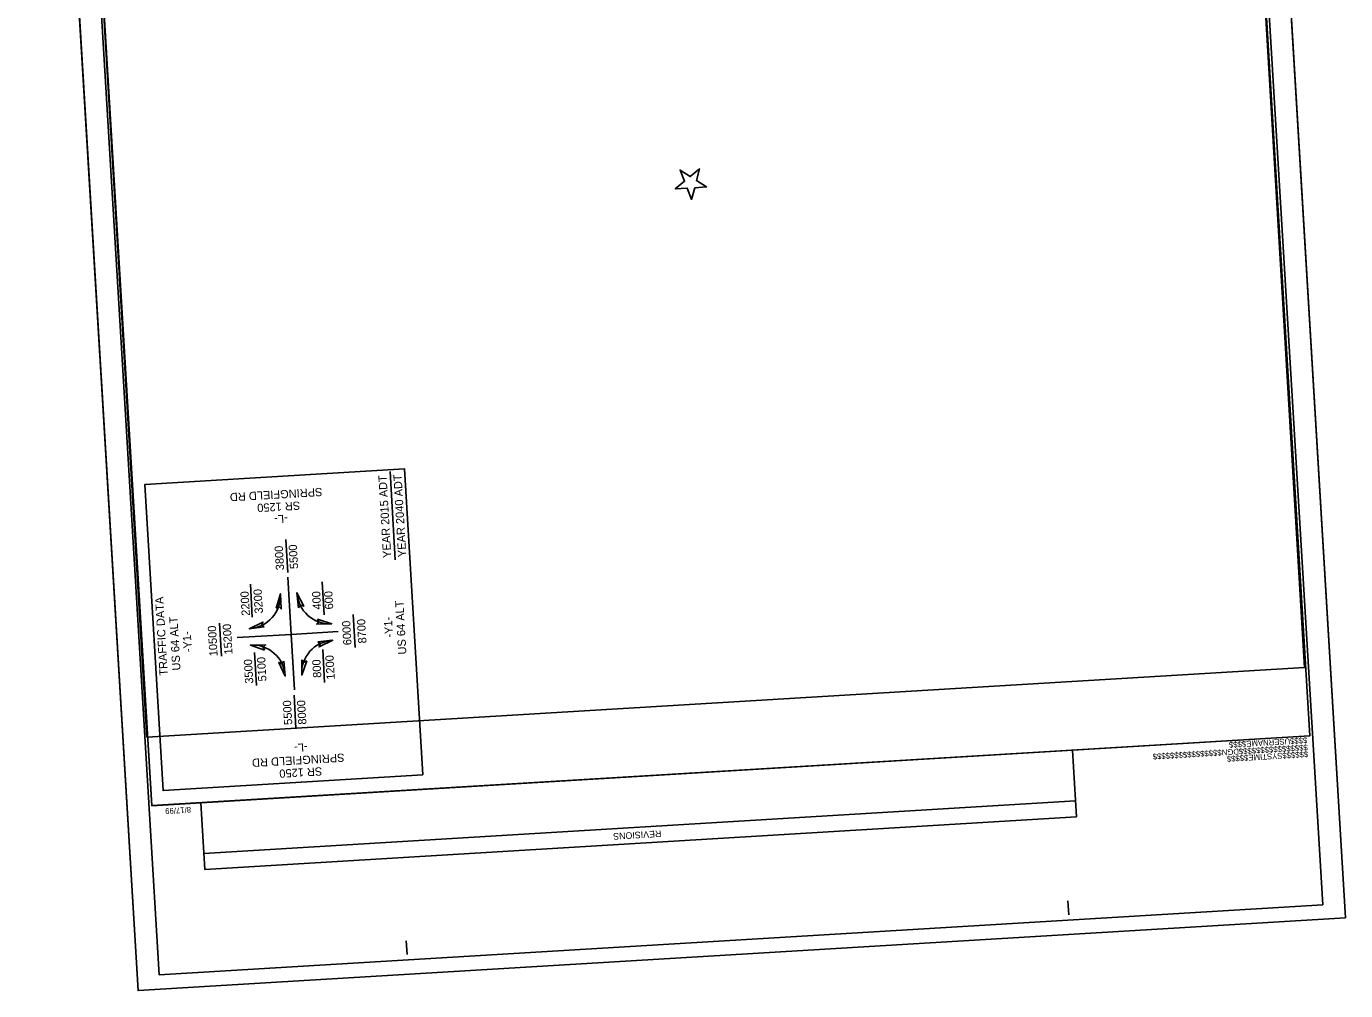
# Model space of a CAD drawing. Extents: x 2368361 to 2369555, y 800599 to 802345.
# Drawn here: x 2368361 to 2369555, y 800599 to 801472 of the extents above; entities that cross this region are included whole.
import ezdxf

# ---------------------------------------------------------------- set-up
doc = ezdxf.new("R2010")
doc.units = 0
for name, color, linetype in [('Old_Level_1', 7, 'Continuous'), ('Old_Level_10', 7, 'Continuous'), ('Old_Level_15', 7, 'Continuous'), ('Old_Level_2', 7, 'Continuous'), ('Old_Level_3', 7, 'Continuous'), ('Old_Level_4', 7, 'Continuous'), ('Old_Level_6', 7, 'Continuous'), ('Old_Level_7', 7, 'Continuous'), ('Plot Shape CELL', 7, 'Continuous'), ('User Information Notes CELL', 7, 'Continuous')]:
    doc.layers.add(name, color=color, linetype=linetype)

msp = doc.modelspace()

# ---------------------------------------------------------------- linework, layer by layer
at = {"layer": 'Old_Level_1'}
msp.add_lwpolyline([(2368966.2, 801326.1), (2368977, 801326.8), (2368967.9, 801332.6), (2368970.6, 801343.2), (2368962.2, 801336.3), (2368953, 801342.1), (2368957, 801332), (2368948.6, 801325.1), (2368959.4, 801325.7), (2368963.4, 801315.6), (2368966.2, 801326.1)], dxfattribs=at)
at = {"layer": 'Old_Level_10'}
msp.add_lwpolyline([(2368474.8, 800766.6), (2369522.9, 800829.7), (2369432.8, 802327), (2368595.8, 802276.7), (2368610.2, 802037.8), (2368399.1, 802025.1)], close=True, dxfattribs=at)
at = {"layer": 'Old_Level_15'}
for p, q in [((2369555.4, 800664.9), (2369454.3, 802345.4)), ((2368361.2, 802279.6), (2368462.3, 800599.1)), ((2368462.3, 800599.1), (2369555.4, 800664.9))]:
    msp.add_line(p, q, dxfattribs=at)
at = {"layer": 'Old_Level_2'}
msp.add_lwpolyline([(2368470.2, 800828.5), (2368399.1, 802025.1), (2368610.2, 802037.8), (2368599.6, 802213.8), (2369302.2, 802249.9), (2369298, 802318.9), (2369432.8, 802327), (2369518.3, 800891.6)], close=True, dxfattribs=at)
msp.add_lwpolyline([(2368470.2, 800828.5), (2368399.1, 802025.1), (2368610.2, 802037.8), (2368599.6, 802213.8), (2369302.2, 802249.9), (2369298, 802318.9), (2369432.8, 802327), (2369518.3, 800891.6)], close=True, dxfattribs=at)
at = {"layer": 'Old_Level_3'}
for points in [[(2368587.2, 800945.5), (2368591.2, 800958.5), (2368591.9, 800944.8), (2368589.7, 800946.8)], [(2368607.7, 800945.8), (2368606.1, 800959.4), (2368612.3, 800947.1), (2368609.5, 800948.1)], [(2368576.5, 800928.4), (2368563, 800926.8), (2368575.3, 800932.9), (2368574.3, 800930.1)], [(2368624.8, 800935.6), (2368637.7, 800931.3), (2368624, 800931), (2368626, 800933.1)], [(2368625, 800915), (2368638.6, 800916.4), (2368626.2, 800910.4), (2368627.2, 800913.2)], [(2368576.8, 800907.5), (2368564, 800912), (2368577.7, 800912.1), (2368575.6, 800910)], [(2368594.2, 800897.5), (2368595.6, 800883.9), (2368589.7, 800896.3), (2368592.4, 800895.3)], [(2368615.2, 800897.6), (2368610.5, 800884.8), (2368610.6, 800898.5), (2368612.6, 800896.4)]]:
    msp.add_lwpolyline(points, close=True, dxfattribs=at)
at = {"layer": 'Old_Level_4'}
msp.add_lwpolyline([(2369534.6, 800676.7), (2369434.6, 802339.6), (2368381.5, 802276.3), (2368481.5, 800613.3)], close=True, dxfattribs=at)
at = {"layer": 'Old_Level_6'}
msp.add_lwpolyline([(2369555.4, 800664.9), (2369454.3, 802345.4), (2368361.2, 802279.6), (2368462.3, 800599.1)], close=True, dxfattribs=at)
at = {"layer": 'Old_Level_7'}
for p, q in [((2368695, 800989.3), (2368690.4, 801069.1)), ((2368597.8, 800977.8), (2368596, 801007.6)), ((2368600.8, 800921.7), (2368597.8, 800973.4)), ((2368565.7, 800937.3), (2368564, 800967.2)), ((2368630.7, 800939.5), (2368628.9, 800969.3)), ((2368658.8, 800909.9), (2368657, 800939.7)), ((2368537.8, 800902), (2368536.1, 800931.8)), ((2368600.8, 800921.7), (2368552.1, 800918.8)), ((2368600.8, 800921.7), (2368643.6, 800924.2)), ((2368603.8, 800871.5), (2368600.8, 800921.7)), ((2368569.5, 800875.4), (2368567.7, 800905.2)), ((2368631.2, 800878.1), (2368629.5, 800907.9)), ((2368605.2, 800836.8), (2368603.5, 800866.7))]:
    msp.add_line(p, q, dxfattribs=at)
msp.add_lwpolyline([(2368720.2, 800794.5), (2368485, 800780.3), (2368468.4, 801057.4), (2368703.5, 801071.5)], close=True, dxfattribs=at)
for centre, start, end in [((2368561.4, 800956.8), 273.3443, 3.3443), ((2368636, 800961.1), 183.3443, 273.3443), ((2368640.3, 800886.5), 93.3443, 183.3443), ((2368565.7, 800882.2), 3.3443, 93.3443)]:
    msp.add_arc(centre, 29.9, start, end, dxfattribs=at)
at = {"layer": 'Plot Shape CELL'}
for p, q in [((2369522.9, 800829.7), (2369522.9, 800829.7)), ((2368474.8, 800766.7), (2368474.8, 800766.7)), ((2369304.7, 800667.9), (2369304, 800680.3)), ((2368705.8, 800631.8), (2368705.1, 800644.3))]:
    msp.add_line(p, q, dxfattribs=at)
for points in [[(2368384.7, 802264), (2368474.8, 800766.7), (2369522.9, 800829.7), (2369432.8, 802327)], [(2369522.9, 800829.7), (2368474.8, 800766.6), (2368396.7, 802064.3), (2368546.5, 802073.3), (2368534.5, 802273), (2369432.8, 802327)]]:
    msp.add_lwpolyline(points, close=True, dxfattribs=at)
at = {"layer": 'User Information Notes CELL'}
msp.add_line((2369311, 800770.9), (2368521.8, 800723.4), dxfattribs=at)
msp.add_lwpolyline([(2369311.9, 800756.4), (2368522.7, 800708.9), (2368519.1, 800769.3), (2369308.3, 800816.8)], close=True, dxfattribs=at)

# ---------------------------------------------------------------- texts
at = {"layer": 'Old_Level_7'}
for s, height, rotation, p in [('YEAR 2015 ADT', 7.471, 93.3443, (2368691.6, 800991.2)), ('YEAR 2040 ADT', 7.471, 93.3443, (2368705.2, 800991.9)), ('SPRINGFIELD RD', 7.471, 183.3443, (2368628.9, 801054.5)), ('SR 1250', 7.47, 183.3443, (2368608.8, 801042.1)), ('-L-', 7.47, 183.3443, (2368597.6, 801030.2)), ('3800', 7.47, 93.3443, (2368594.6, 800980)), ('5500', 7.47, 93.3443, (2368607.3, 800981.1)), ('2200', 7.47, 93.3443, (2368563.6, 800938.8)), ('3200', 7.47, 93.3443, (2368575.4, 800940.8)), ('400', 7.47, 93.3443, (2368628.1, 800944.4)), ('600', 7.47, 93.3443, (2368639.1, 800944.5)), ('TRAFFIC DATA', 7.471, 93.3443, (2368489.3, 800884.5)), ('US 64 ALT', 7.47, 93.3443, (2368705.3, 800903.7)), ('US 64 ALT', 7.47, 93.3443, (2368500.8, 800889.2)), ('-Y1-', 7.47, 93.3443, (2368693.2, 800919)), ('10500', 7.47, 93.3443, (2368534.4, 800902.1)), ('15200', 7.47, 93.3443, (2368547.9, 800903.7)), ('6000', 7.47, 93.3443, (2368655.6, 800912.1)), ('8700', 7.47, 93.3443, (2368669.1, 800913.7)), ('-Y1-', 7.47, 93.3443, (2368511.1, 800905.8)), ('5100', 7.47, 93.3443, (2368578.6, 800879.3)), ('1200', 7.47, 93.3443, (2368640.5, 800880.9)), ('3500', 7.47, 93.3443, (2368566.7, 800877.3)), ('800', 7.47, 93.3443, (2368628.3, 800882.6)), ('5500', 7.47, 93.3443, (2368602, 800840)), ('8000', 7.47, 93.3443, (2368614.8, 800840.2)), ('-L-', 7.47, 183.3443, (2368615.6, 800823.2)), ('SPRINGFIELD RD', 7.471, 183.3443, (2368648.9, 800813.9)), ('SR 1250', 7.47, 183.3443, (2368628.8, 800801.5))]:
    msp.add_text(s, height=height, rotation=rotation, dxfattribs=at).set_placement(p)
at = {"layer": 'Plot Shape CELL'}
for s, p in [('$$$$USERNAME$$$$', (2369520.6, 800828.5)), ('$$$$$$$$$$$$$$$$DGN$$$$$$$$$$$$$$$$', (2369521, 800822)), ('$$$$$$SYSTIME$$$$$', (2369521.4, 800815.9)), ('8/17/99', (2368510.1, 800765.6))]:
    msp.add_text(s, height=5.25, rotation=183.443, dxfattribs=at).set_placement(p)
at = {"layer": 'User Information Notes CELL'}
msp.add_text('REVISIONS', height=6, rotation=183.443, dxfattribs=at).set_placement((2368935.8, 800744.3))

doc.saveas('drawing.dxf')
